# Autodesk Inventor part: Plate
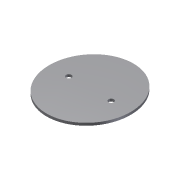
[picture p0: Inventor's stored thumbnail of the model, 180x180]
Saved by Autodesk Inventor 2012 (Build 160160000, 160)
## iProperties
Created: 2009-04
Part Number: Plate
Document SubType Name: Modeling
Designer: Sham
Density: 1 g/cm^3
Material: Default
Author: Sham
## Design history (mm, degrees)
sketch "Sketch1"
  geometry: C1 r 6.25 at (-50, 0); C2 r 6.25 at (50, 0); 4 further points; 1 other entity
  constraints: 2 centre point, 1 coincident, 5 other
  dimensions: "d1" = 12.5 diameter of C1; "d2" = 12.5 diameter of C2; "d3" = 100 distance of C2.centre C1.centre; "d4" = 102.5 distance of point (0, 0) point (0, 102.5); "d5" = 96 distance of point (0, 0) point (-96, 0); "d6" = 50 distance of point (0, 0) C1.centre
extrude "Extrusion1" new body sketch "Sketch1" distance "d7" = 6; taper "d8" = 0 deg
body "Solid1"
